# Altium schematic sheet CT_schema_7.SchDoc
size 382 x 278 mm
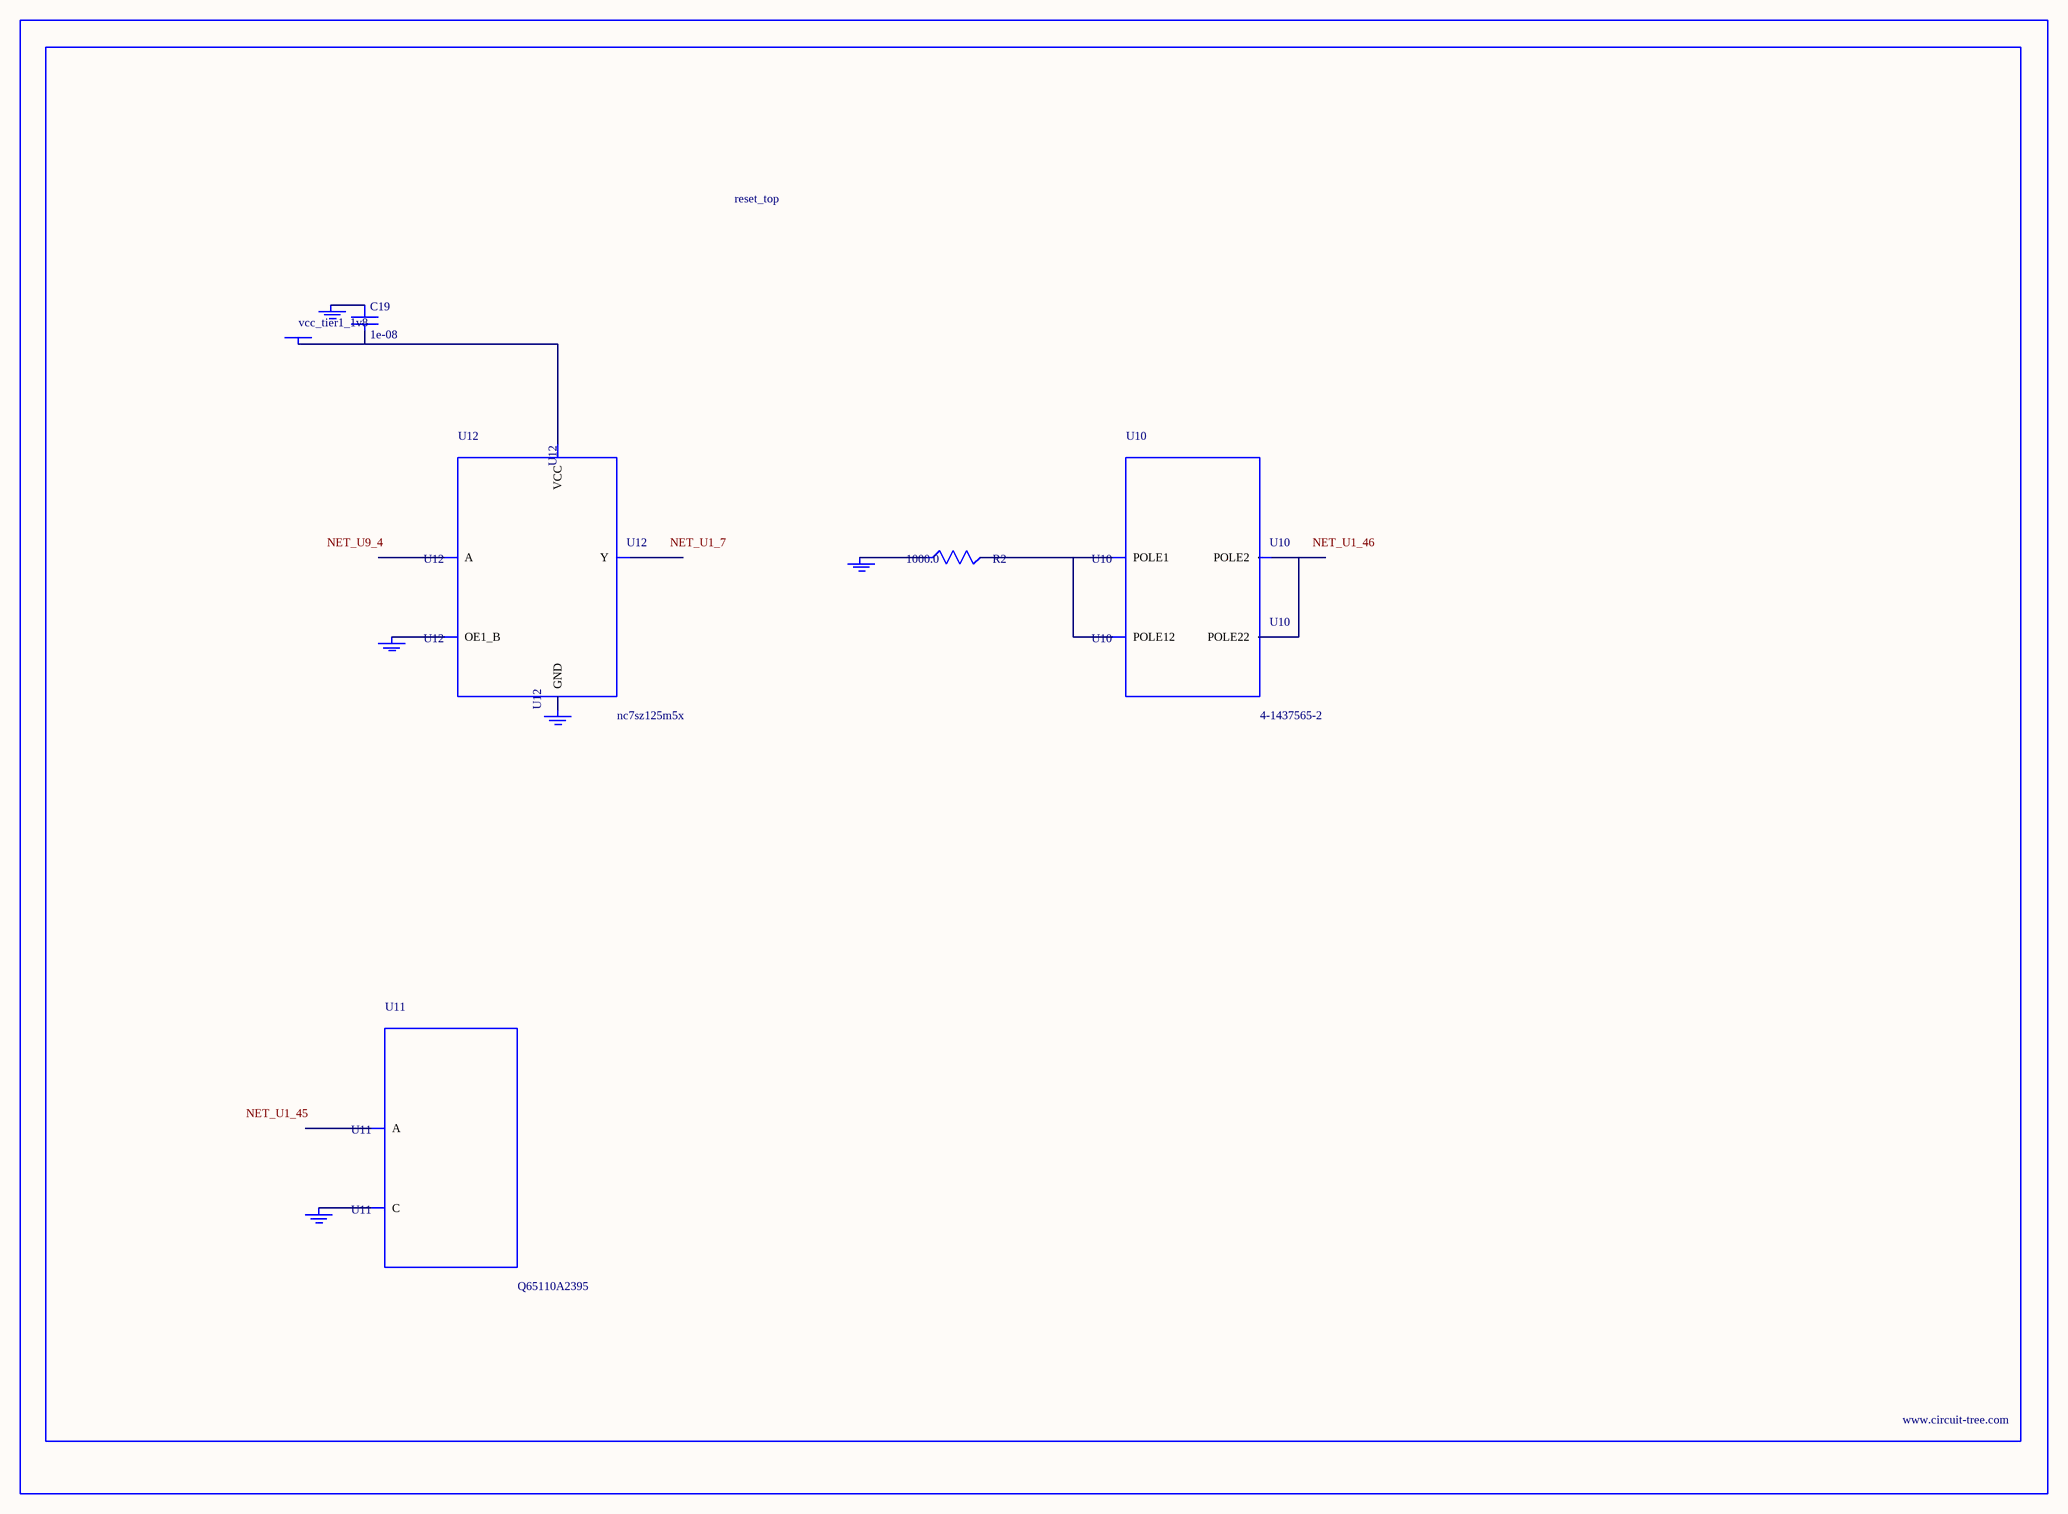
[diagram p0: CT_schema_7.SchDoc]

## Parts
BORDER6  (no value)
C19  1e-08  [C0402]
GND_INSTANCE_6_0  (no value)
GND_INSTANCE_6_1  (no value)
GND_INSTANCE_6_2  (no value)
GND_INSTANCE_6_3  (no value)
GND_INSTANCE_6_4  (no value)
POWER_INSTANCE_6_0  vcc_tier1_1v8
R2  1000.0  [R0603]
U10  4-1437565-2  [SW_4-1437565-2]
U11  Q65110A2395  [LGM67K-G1J2-24-Z]
U12  nc7sz125m5x  [NC7SZ125M5X]

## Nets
NetC19_1: C19.1 GND_INSTANCE_6_2.0(GND)
NetC19_2: C19.2 POWER_INSTANCE_6_0.0(PWR) U12.5(VCC)
NetGND_INSTANCE_6_0_0: GND_INSTANCE_6_0.0(GND) R2.1
NetGND_INSTANCE_6_1_0: GND_INSTANCE_6_1.0(GND) U11.C
NetGND_INSTANCE_6_3_0: GND_INSTANCE_6_3.0(GND) U12.1(OE1_B)
NetGND_INSTANCE_6_4_0: GND_INSTANCE_6_4.0(GND) U12.3(GND)
NetR2_2: R2.2 U10.1(POLE1) U10.2(POLE12)
NetU10_3: U10.3(POLE2) U10.4(POLE22)

Not connected (* = marked no-connect by the designer): U11 A; U12 2(A) 4(Y)

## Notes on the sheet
- Labels drawn without touching a wire or pin: NET_U1_7, NET_U1_45, NET_U1_46, NET_U9_4

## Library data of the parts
BORDER6 = BORDER_PAGE6
C19 = C0402C103K3RAC
GND_INSTANCE_6_0-GND_INSTANCE_6_4 = GND
POWER_INSTANCE_6_0 = PWR
R2 = RC0603JR-071KL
